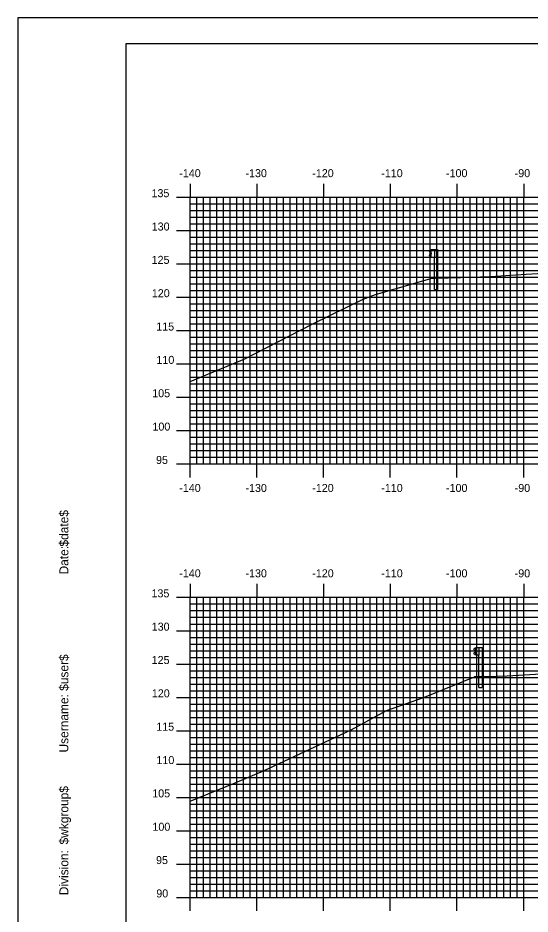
# Model space of a CAD drawing. Extents: x 858052 to 858395, y 364366 to 364586.
# Drawn here: x 858051.6 to 858128.3, y 364451.3 to 364585.7 of the extents above; entities that cross this region are included whole.
import ezdxf

# ---------------------------------------------------------------- set-up
doc = ezdxf.new("R2010")
doc.units = 0
for name, color, linetype in [('BORDER', 7, 'Continuous'), ('H_V ANNOTATION', 7, 'Continuous'), ('M_Guardrail', 7, 'Continuous'), ('MAJOR', 7, 'Continuous'), ('MINOR', 7, 'Continuous'), ('PLOT BOUNDARY', 7, 'Continuous'), ('S_Roadway_Centerline', 7, 'Continuous')]:
    doc.layers.add(name, color=color, linetype=linetype)

msp = doc.modelspace()

# ---------------------------------------------------------------- linework, layer by layer
at = {"layer": 'BORDER'}
msp.add_lwpolyline([(858067.76, 364371.79), (858387.76, 364371.79), (858387.76, 364581.79), (858067.76, 364581.79)], close=True, dxfattribs=at)
at = {"layer": 'M_Guardrail'}
for p, q in [((858113.39, 364550.84), (858113.25, 364550.74)), ((858113.49, 364550.86), (858113.41, 364550.85)), ((858113.49, 364550.93), (858113.98, 364550.93)), ((858113.49, 364549.77), (858113.49, 364550.93)), ((858113.98, 364550.93), (858114.47, 364550.93)), ((858113.98, 364550.93), (858113.98, 364549.77)), ((858114.47, 364550.93), (858114.47, 364544.93)), ((858113.25, 364550.6), (858113.45, 364550.46)), ((858113.45, 364550.24), (858113.25, 364550.1)), ((858113.25, 364549.96), (858113.39, 364549.86)), ((858113.41, 364549.85), (858113.49, 364549.84)), ((858113.48, 364550.39), (858113.48, 364550.3)), ((858113.98, 364549.77), (858113.49, 364549.77)), ((858113.98, 364544.93), (858113.98, 364549.77)), ((858113.98, 364544.93), (858114.47, 364544.93)), ((858120.07, 364491.18), (858119.93, 364491.08)), ((858119.93, 364490.94), (858120.13, 364490.8)), ((858120.13, 364490.58), (858119.93, 364490.45)), ((858119.93, 364490.31), (858120.07, 364490.21)), ((858120.17, 364491.2), (858120.09, 364491.19)), ((858120.16, 364490.74), (858120.16, 364490.65)), ((858120.17, 364491.28), (858120.66, 364491.28)), ((858120.17, 364490.11), (858120.17, 364491.28)), ((858120.66, 364491.28), (858121.15, 364491.28)), ((858120.66, 364491.28), (858120.66, 364490.11)), ((858121.15, 364491.28), (858121.15, 364485.28)), ((858120.09, 364490.2), (858120.17, 364490.18)), ((858120.66, 364490.11), (858120.17, 364490.11)), ((858120.66, 364485.28), (858120.66, 364490.11)), ((858120.66, 364485.28), (858121.15, 364485.28))]:
    msp.add_line(p, q, dxfattribs=at)
for centre, major_axis, start_param, end_param in [((858113.3, 364550.67), (-0.0877, 0), 5.323254, 7.243116), ((858113.42, 364550.8), (-0.0417, 0), 4.886922, 5.323254), ((858113.3, 364550.03), (-0.0877, 0), 5.323254, 7.243116), ((858113.42, 364549.89), (-0.0417, 0), 0.959931, 1.396263), ((858113.4, 364550.39), (0.0789, 0), 0, 0.959931), ((858113.4, 364550.3), (0.0789, 0), 5.323254, 6.283185), ((858119.98, 364491.01), (-0.0877, 0), 5.323254, 7.243116), ((858119.98, 364490.38), (-0.0877, 0), 5.323254, 7.243116), ((858120.1, 364491.15), (-0.0417, 0), 4.886922, 5.323254), ((858120.08, 364490.74), (0.0789, 0), 0, 0.959931), ((858120.08, 364490.65), (0.0789, 0), 5.323254, 6.283185), ((858120.1, 364490.24), (-0.0417, 0), 0.959931, 1.396263)]:
    msp.add_ellipse(centre, major_axis=major_axis, ratio=0.995501, start_param=start_param, end_param=end_param, dxfattribs=at)
at = {"layer": 'MAJOR'}
for p, q in [((858077.36, 364560.79), (858077.36, 364558.79)), ((858087.36, 364560.79), (858087.36, 364558.79)), ((858097.36, 364560.79), (858097.36, 364558.79)), ((858107.36, 364560.79), (858107.36, 364558.79)), ((858117.36, 364560.79), (858117.36, 364558.79)), ((858127.36, 364560.79), (858127.36, 364558.79)), ((858075.36, 364558.79), (858077.36, 364558.79)), ((858077.36, 364558.79), (858357.36, 364558.79)), ((858077.36, 364518.79), (858077.36, 364558.79)), ((858077.36, 364518.79), (858077.36, 364558.79)), ((858077.36, 364558.79), (858357.36, 364558.79)), ((858087.36, 364518.79), (858087.36, 364558.79)), ((858097.36, 364518.79), (858097.36, 364558.79)), ((858107.36, 364518.79), (858107.36, 364558.79)), ((858117.36, 364518.79), (858117.36, 364558.79)), ((858127.36, 364518.79), (858127.36, 364558.79)), ((858075.36, 364553.79), (858077.36, 364553.79)), ((858077.36, 364553.79), (858357.36, 364553.79)), ((858075.36, 364548.79), (858077.36, 364548.79)), ((858077.36, 364548.79), (858357.36, 364548.79)), ((858075.36, 364543.79), (858077.36, 364543.79)), ((858077.36, 364543.79), (858357.36, 364543.79)), ((858075.36, 364538.79), (858077.36, 364538.79)), ((858077.36, 364538.79), (858357.36, 364538.79)), ((858075.36, 364533.79), (858077.36, 364533.79)), ((858077.36, 364533.79), (858357.36, 364533.79)), ((858075.36, 364528.79), (858077.36, 364528.79)), ((858077.36, 364528.79), (858357.36, 364528.79)), ((858075.36, 364523.79), (858077.36, 364523.79)), ((858077.36, 364523.79), (858357.36, 364523.79)), ((858075.36, 364518.79), (858077.36, 364518.79)), ((858077.36, 364518.79), (858357.36, 364518.79)), ((858077.36, 364518.79), (858357.36, 364518.79)), ((858077.36, 364516.78), (858077.36, 364518.79)), ((858087.36, 364516.78), (858087.36, 364518.79)), ((858097.36, 364516.78), (858097.36, 364518.79)), ((858107.36, 364516.78), (858107.36, 364518.79)), ((858117.36, 364516.78), (858117.36, 364518.79)), ((858127.36, 364516.78), (858127.36, 364518.79)), ((858077.36, 364500.79), (858077.36, 364498.79)), ((858087.36, 364500.79), (858087.36, 364498.79)), ((858097.36, 364500.79), (858097.36, 364498.79)), ((858107.36, 364500.79), (858107.36, 364498.79)), ((858117.36, 364500.79), (858117.36, 364498.79)), ((858127.36, 364500.79), (858127.36, 364498.79)), ((858075.36, 364498.79), (858077.36, 364498.79)), ((858077.36, 364498.79), (858357.36, 364498.79)), ((858077.36, 364453.79), (858077.36, 364498.79)), ((858077.36, 364453.79), (858077.36, 364498.79)), ((858077.36, 364498.79), (858357.36, 364498.79)), ((858087.36, 364453.79), (858087.36, 364498.79)), ((858097.36, 364453.79), (858097.36, 364498.79)), ((858107.36, 364453.79), (858107.36, 364498.79)), ((858117.36, 364453.79), (858117.36, 364498.79)), ((858127.36, 364453.79), (858127.36, 364498.79)), ((858075.36, 364493.79), (858077.36, 364493.79)), ((858077.36, 364493.79), (858357.36, 364493.79)), ((858075.36, 364488.79), (858077.36, 364488.79)), ((858077.36, 364488.79), (858357.36, 364488.79)), ((858075.36, 364483.79), (858077.36, 364483.79)), ((858077.36, 364483.79), (858357.36, 364483.79)), ((858075.36, 364478.79), (858077.36, 364478.79)), ((858077.36, 364478.79), (858357.36, 364478.79)), ((858075.36, 364473.79), (858077.36, 364473.79)), ((858077.36, 364473.79), (858357.36, 364473.79)), ((858075.36, 364468.79), (858077.36, 364468.79)), ((858077.36, 364468.79), (858357.36, 364468.79)), ((858075.36, 364463.79), (858077.36, 364463.79)), ((858077.36, 364463.79), (858357.36, 364463.79)), ((858075.36, 364458.79), (858077.36, 364458.79)), ((858077.36, 364458.79), (858357.36, 364458.79)), ((858075.36, 364453.79), (858077.36, 364453.79)), ((858077.36, 364453.79), (858357.36, 364453.79)), ((858077.36, 364453.79), (858357.36, 364453.79)), ((858077.36, 364451.78), (858077.36, 364453.79)), ((858087.36, 364451.78), (858087.36, 364453.79)), ((858097.36, 364451.78), (858097.36, 364453.79)), ((858107.36, 364451.78), (858107.36, 364453.79)), ((858117.36, 364451.78), (858117.36, 364453.79)), ((858127.36, 364451.78), (858127.36, 364453.79))]:
    msp.add_line(p, q, dxfattribs=at)
at = {"layer": 'MINOR'}
for p, q in [((858078.36, 364518.79), (858078.36, 364558.79)), ((858079.36, 364518.79), (858079.36, 364558.79)), ((858080.36, 364518.79), (858080.36, 364558.79)), ((858081.36, 364518.79), (858081.36, 364558.79)), ((858082.36, 364518.79), (858082.36, 364558.79)), ((858083.36, 364518.79), (858083.36, 364558.79)), ((858084.36, 364518.79), (858084.36, 364558.79)), ((858085.36, 364518.79), (858085.36, 364558.79)), ((858086.36, 364518.79), (858086.36, 364558.79)), ((858088.36, 364518.79), (858088.36, 364558.79)), ((858089.36, 364518.79), (858089.36, 364558.79)), ((858090.36, 364518.79), (858090.36, 364558.79)), ((858091.36, 364518.79), (858091.36, 364558.79)), ((858092.36, 364518.79), (858092.36, 364558.79)), ((858093.36, 364518.79), (858093.36, 364558.79)), ((858094.36, 364518.79), (858094.36, 364558.79)), ((858095.36, 364518.79), (858095.36, 364558.79)), ((858096.36, 364518.79), (858096.36, 364558.79)), ((858098.36, 364518.79), (858098.36, 364558.79)), ((858099.36, 364518.79), (858099.36, 364558.79)), ((858100.36, 364518.79), (858100.36, 364558.79)), ((858101.36, 364518.79), (858101.36, 364558.79)), ((858102.36, 364518.79), (858102.36, 364558.79)), ((858103.36, 364518.79), (858103.36, 364558.79)), ((858104.36, 364518.79), (858104.36, 364558.79)), ((858105.36, 364518.79), (858105.36, 364558.79)), ((858106.36, 364518.79), (858106.36, 364558.79)), ((858108.36, 364518.79), (858108.36, 364558.79)), ((858109.36, 364518.79), (858109.36, 364558.79)), ((858110.36, 364518.79), (858110.36, 364558.79)), ((858111.36, 364518.79), (858111.36, 364558.79)), ((858112.36, 364518.79), (858112.36, 364558.79)), ((858113.36, 364518.79), (858113.36, 364558.79)), ((858114.36, 364518.79), (858114.36, 364558.79)), ((858115.36, 364518.79), (858115.36, 364558.79)), ((858116.36, 364518.79), (858116.36, 364558.79)), ((858118.36, 364518.79), (858118.36, 364558.79)), ((858119.36, 364518.79), (858119.36, 364558.79)), ((858120.36, 364518.79), (858120.36, 364558.79)), ((858121.36, 364518.79), (858121.36, 364558.79)), ((858122.36, 364518.79), (858122.36, 364558.79)), ((858123.36, 364518.79), (858123.36, 364558.79)), ((858124.36, 364518.79), (858124.36, 364558.79)), ((858125.36, 364518.79), (858125.36, 364558.79)), ((858126.36, 364518.79), (858126.36, 364558.79)), ((858077.36, 364557.79), (858357.36, 364557.79)), ((858077.36, 364557.79), (858079.37, 364557.79)), ((858077.36, 364556.79), (858357.36, 364556.79)), ((858077.36, 364556.79), (858079.37, 364556.79)), ((858077.36, 364555.79), (858357.36, 364555.79)), ((858077.36, 364555.79), (858079.37, 364555.79)), ((858077.36, 364554.79), (858357.36, 364554.79)), ((858077.36, 364554.79), (858079.37, 364554.79)), ((858077.36, 364552.79), (858357.36, 364552.79)), ((858077.36, 364552.79), (858079.37, 364552.79)), ((858077.36, 364551.79), (858357.36, 364551.79)), ((858077.36, 364551.79), (858079.37, 364551.79)), ((858077.36, 364550.79), (858357.36, 364550.79)), ((858077.36, 364550.79), (858079.37, 364550.79)), ((858077.36, 364549.79), (858357.36, 364549.79)), ((858077.36, 364549.79), (858079.37, 364549.79)), ((858077.36, 364547.79), (858357.36, 364547.79)), ((858077.36, 364547.79), (858079.37, 364547.79)), ((858077.36, 364546.79), (858357.36, 364546.79)), ((858077.36, 364546.79), (858079.37, 364546.79)), ((858077.36, 364545.79), (858357.36, 364545.79)), ((858077.36, 364545.79), (858079.37, 364545.79)), ((858077.36, 364544.79), (858357.36, 364544.79)), ((858077.36, 364544.79), (858079.37, 364544.79)), ((858077.36, 364542.79), (858357.36, 364542.79)), ((858077.36, 364542.79), (858079.37, 364542.79)), ((858077.36, 364541.79), (858357.36, 364541.79)), ((858077.36, 364541.79), (858079.37, 364541.79)), ((858077.36, 364540.79), (858357.36, 364540.79)), ((858077.36, 364540.79), (858079.37, 364540.79)), ((858077.36, 364539.79), (858357.36, 364539.79)), ((858077.36, 364539.79), (858079.37, 364539.79)), ((858077.36, 364537.79), (858357.36, 364537.79)), ((858077.36, 364537.79), (858079.37, 364537.79)), ((858077.36, 364536.79), (858357.36, 364536.79)), ((858077.36, 364536.79), (858079.37, 364536.79)), ((858077.36, 364535.79), (858357.36, 364535.79)), ((858077.36, 364535.79), (858079.37, 364535.79)), ((858077.36, 364534.79), (858357.36, 364534.79)), ((858077.36, 364534.79), (858079.37, 364534.79)), ((858077.36, 364532.79), (858357.36, 364532.79)), ((858077.36, 364532.79), (858079.37, 364532.79)), ((858077.36, 364531.79), (858357.36, 364531.79)), ((858077.36, 364531.79), (858079.37, 364531.79)), ((858077.36, 364530.79), (858357.36, 364530.79)), ((858077.36, 364530.79), (858079.37, 364530.79)), ((858077.36, 364529.79), (858357.36, 364529.79)), ((858077.36, 364529.79), (858079.37, 364529.79)), ((858077.36, 364527.79), (858357.36, 364527.79)), ((858077.36, 364527.79), (858079.37, 364527.79)), ((858077.36, 364526.79), (858357.36, 364526.79)), ((858077.36, 364526.79), (858079.37, 364526.79)), ((858077.36, 364525.79), (858357.36, 364525.79)), ((858077.36, 364525.79), (858079.37, 364525.79)), ((858077.36, 364524.79), (858357.36, 364524.79)), ((858077.36, 364524.79), (858079.37, 364524.79)), ((858077.36, 364522.79), (858357.36, 364522.79)), ((858077.36, 364522.79), (858079.37, 364522.79)), ((858077.36, 364521.79), (858357.36, 364521.79)), ((858077.36, 364521.79), (858079.37, 364521.79)), ((858077.36, 364520.79), (858357.36, 364520.79)), ((858077.36, 364520.79), (858079.37, 364520.79)), ((858077.36, 364519.79), (858357.36, 364519.79)), ((858077.36, 364519.79), (858079.37, 364519.79)), ((858078.36, 364453.79), (858078.36, 364498.79)), ((858079.36, 364453.79), (858079.36, 364498.79)), ((858080.36, 364453.79), (858080.36, 364498.79)), ((858081.36, 364453.79), (858081.36, 364498.79)), ((858082.36, 364453.79), (858082.36, 364498.79)), ((858083.36, 364453.79), (858083.36, 364498.79)), ((858084.36, 364453.79), (858084.36, 364498.79)), ((858085.36, 364453.79), (858085.36, 364498.79)), ((858086.36, 364453.79), (858086.36, 364498.79)), ((858088.36, 364453.79), (858088.36, 364498.79)), ((858089.36, 364453.79), (858089.36, 364498.79)), ((858090.36, 364453.79), (858090.36, 364498.79)), ((858091.36, 364453.79), (858091.36, 364498.79)), ((858092.36, 364453.79), (858092.36, 364498.79)), ((858093.36, 364453.79), (858093.36, 364498.79)), ((858094.36, 364453.79), (858094.36, 364498.79)), ((858095.36, 364453.79), (858095.36, 364498.79)), ((858096.36, 364453.79), (858096.36, 364498.79)), ((858098.36, 364453.79), (858098.36, 364498.79)), ((858099.36, 364453.79), (858099.36, 364498.79)), ((858100.36, 364453.79), (858100.36, 364498.79)), ((858101.36, 364453.79), (858101.36, 364498.79)), ((858102.36, 364453.79), (858102.36, 364498.79)), ((858103.36, 364453.79), (858103.36, 364498.79)), ((858104.36, 364453.79), (858104.36, 364498.79)), ((858105.36, 364453.79), (858105.36, 364498.79)), ((858106.36, 364453.79), (858106.36, 364498.79)), ((858108.36, 364453.79), (858108.36, 364498.79)), ((858109.36, 364453.79), (858109.36, 364498.79)), ((858110.36, 364453.79), (858110.36, 364498.79)), ((858111.36, 364453.79), (858111.36, 364498.79)), ((858112.36, 364453.79), (858112.36, 364498.79)), ((858113.36, 364453.79), (858113.36, 364498.79)), ((858114.36, 364453.79), (858114.36, 364498.79)), ((858115.36, 364453.79), (858115.36, 364498.79)), ((858116.36, 364453.79), (858116.36, 364498.79)), ((858118.36, 364453.79), (858118.36, 364498.79)), ((858119.36, 364453.79), (858119.36, 364498.79)), ((858120.36, 364453.79), (858120.36, 364498.79)), ((858121.36, 364453.79), (858121.36, 364498.79)), ((858122.36, 364453.79), (858122.36, 364498.79)), ((858123.36, 364453.79), (858123.36, 364498.79)), ((858124.36, 364453.79), (858124.36, 364498.79)), ((858125.36, 364453.79), (858125.36, 364498.79)), ((858126.36, 364453.79), (858126.36, 364498.79)), ((858077.36, 364497.79), (858357.36, 364497.79)), ((858077.36, 364497.79), (858079.37, 364497.79)), ((858077.36, 364496.79), (858357.36, 364496.79)), ((858077.36, 364496.79), (858079.37, 364496.79)), ((858077.36, 364495.79), (858357.36, 364495.79)), ((858077.36, 364495.79), (858079.37, 364495.79)), ((858077.36, 364494.79), (858357.36, 364494.79)), ((858077.36, 364494.79), (858079.37, 364494.79)), ((858077.36, 364492.79), (858357.36, 364492.79)), ((858077.36, 364492.79), (858079.37, 364492.79)), ((858077.36, 364491.79), (858357.36, 364491.79)), ((858077.36, 364491.79), (858079.37, 364491.79)), ((858077.36, 364490.79), (858357.36, 364490.79)), ((858077.36, 364490.79), (858079.37, 364490.79)), ((858077.36, 364489.79), (858357.36, 364489.79)), ((858077.36, 364489.79), (858079.37, 364489.79)), ((858077.36, 364487.79), (858357.36, 364487.79)), ((858077.36, 364487.79), (858079.37, 364487.79)), ((858077.36, 364486.79), (858357.36, 364486.79)), ((858077.36, 364486.79), (858079.37, 364486.79)), ((858077.36, 364485.79), (858357.36, 364485.79)), ((858077.36, 364485.79), (858079.37, 364485.79)), ((858077.36, 364484.79), (858357.36, 364484.79)), ((858077.36, 364484.79), (858079.37, 364484.79)), ((858077.36, 364482.79), (858357.36, 364482.79)), ((858077.36, 364482.79), (858079.37, 364482.79)), ((858077.36, 364481.79), (858357.36, 364481.79)), ((858077.36, 364481.79), (858079.37, 364481.79)), ((858077.36, 364480.79), (858357.36, 364480.79)), ((858077.36, 364480.79), (858079.37, 364480.79)), ((858077.36, 364479.79), (858357.36, 364479.79)), ((858077.36, 364479.79), (858079.37, 364479.79)), ((858077.36, 364477.79), (858357.36, 364477.79)), ((858077.36, 364477.79), (858079.37, 364477.79)), ((858077.36, 364476.79), (858357.36, 364476.79)), ((858077.36, 364476.79), (858079.37, 364476.79)), ((858077.36, 364475.79), (858357.36, 364475.79)), ((858077.36, 364475.79), (858079.37, 364475.79)), ((858077.36, 364474.79), (858357.36, 364474.79)), ((858077.36, 364474.79), (858079.37, 364474.79)), ((858077.36, 364472.79), (858357.36, 364472.79)), ((858077.36, 364472.79), (858079.37, 364472.79)), ((858077.36, 364471.79), (858357.36, 364471.79)), ((858077.36, 364471.79), (858079.37, 364471.79)), ((858077.36, 364470.79), (858357.36, 364470.79)), ((858077.36, 364470.79), (858079.37, 364470.79)), ((858077.36, 364469.79), (858357.36, 364469.79)), ((858077.36, 364469.79), (858079.37, 364469.79)), ((858077.36, 364467.79), (858357.36, 364467.79)), ((858077.36, 364467.79), (858079.37, 364467.79)), ((858077.36, 364466.79), (858357.36, 364466.79)), ((858077.36, 364466.79), (858079.37, 364466.79)), ((858077.36, 364465.79), (858357.36, 364465.79)), ((858077.36, 364465.79), (858079.37, 364465.79)), ((858077.36, 364464.79), (858357.36, 364464.79)), ((858077.36, 364464.79), (858079.37, 364464.79)), ((858077.36, 364462.79), (858357.36, 364462.79)), ((858077.36, 364462.79), (858079.37, 364462.79)), ((858077.36, 364461.79), (858357.36, 364461.79)), ((858077.36, 364461.79), (858079.37, 364461.79)), ((858077.36, 364460.79), (858357.36, 364460.79)), ((858077.36, 364460.79), (858079.37, 364460.79)), ((858077.36, 364459.79), (858357.36, 364459.79)), ((858077.36, 364459.79), (858079.37, 364459.79)), ((858077.36, 364457.79), (858357.36, 364457.79)), ((858077.36, 364457.79), (858079.37, 364457.79)), ((858077.36, 364456.79), (858357.36, 364456.79)), ((858077.36, 364456.79), (858079.37, 364456.79)), ((858077.36, 364455.79), (858357.36, 364455.79)), ((858077.36, 364455.79), (858079.37, 364455.79)), ((858077.36, 364454.79), (858357.36, 364454.79)), ((858077.36, 364454.79), (858079.37, 364454.79))]:
    msp.add_line(p, q, dxfattribs=at)
at = {"layer": 'PLOT BOUNDARY'}
msp.add_lwpolyline([(858051.57, 364365.67), (858391.57, 364365.67), (858391.57, 364585.67), (858051.57, 364585.67)], close=True, dxfattribs=at)
at = {"layer": 'S_Roadway_Centerline'}
for points in [[(858077.36, 364531.14), (858081.48, 364532.86), (858085.58, 364534.55), (858095.78, 364539.79), (858103.31, 364543.49), (858105.15, 364544.18), (858113.43, 364546.6), (858114.14, 364546.63), (858117.94, 364546.75), (858122.4, 364546.9), (858127.75, 364547.23), (858131.14, 364547.46)], [(858077.36, 364468.22), (858084.15, 364470.99), (858088.37, 364472.76), (858101.49, 364478.94), (858106.81, 364481.81), (858112.5, 364483.81), (858120, 364486.88), (858120.04, 364486.91), (858123.43, 364486.97), (858124.86, 364487.02), (858125.73, 364487.08), (858136.7, 364487.71)]]:
    msp.add_lwpolyline(points, dxfattribs=at)

# ---------------------------------------------------------------- texts
at = {"layer": 'BORDER'}
for s, p in [('$date$', (858059.13, 364506.4)), ('Date:', (858059.13, 364502.22)), ('$user$', (858059.13, 364484.77)), ('Username:', (858059.13, 364475.52)), ('$wkgroup$', (858059.13, 364461.73)), ('Division:', (858059.13, 364454.12))]:
    msp.add_text(s, height=1.339, rotation=90, dxfattribs=at).set_placement(p)
at = {"layer": 'H_V ANNOTATION'}
for s, p in [('-140', (858075.75, 364561.79)), ('-130', (858085.67, 364561.79)), ('-120', (858095.68, 364561.79)), ('-110', (858106.02, 364561.79)), ('-100', (858115.72, 364561.79)), ('-90', (858126.01, 364561.79)), ('135', (858071.59, 364558.79)), ('130', (858071.62, 364553.79)), ('125', (858071.61, 364548.79)), ('120', (858071.64, 364543.79)), ('115', (858072.3, 364538.79)), ('110', (858072.33, 364533.79)), ('105', (858071.7, 364528.79)), ('100', (858071.73, 364523.79)), ('95', (858072.27, 364518.79)), ('-140', (858075.75, 364514.59)), ('-130', (858085.67, 364514.59)), ('-120', (858095.68, 364514.59)), ('-110', (858106.02, 364514.59)), ('-100', (858115.72, 364514.59)), ('-90', (858126.01, 364514.59)), ('-140', (858075.75, 364501.79)), ('-130', (858085.67, 364501.79)), ('-120', (858095.68, 364501.79)), ('-110', (858106.02, 364501.79)), ('-100', (858115.72, 364501.79)), ('-90', (858126.01, 364501.79)), ('135', (858071.59, 364498.79)), ('130', (858071.62, 364493.79)), ('125', (858071.61, 364488.79)), ('120', (858071.64, 364483.79)), ('115', (858072.3, 364478.79)), ('110', (858072.33, 364473.79)), ('105', (858071.7, 364468.79)), ('100', (858071.73, 364463.79)), ('95', (858072.27, 364458.79)), ('90', (858072.31, 364453.79))]:
    msp.add_text(s, height=1.2, dxfattribs=at).set_placement(p)
at = {"layer": 'MAJOR'}
for p in [(858077.35, 364518.79), (858077.35, 364453.79)]:
    msp.add_text('-', height=0.012, dxfattribs=at).set_placement(p)

doc.saveas('drawing.dxf')
